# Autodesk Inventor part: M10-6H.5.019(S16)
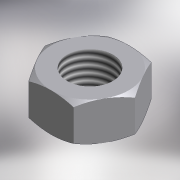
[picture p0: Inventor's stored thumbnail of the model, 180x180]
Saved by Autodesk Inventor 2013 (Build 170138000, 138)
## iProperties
Shininess: 0.0
Length Units: 11269
Angle Units: 11279
Time Units: 11290
Mass Units: 11283
Length Display Precision: 3
Angle Display Precision: 2
Created: 2001-04
Material: Steel, Mild
Description: Гайка М10-6H.5.019 (S16) ГОСТ 5915-70
Document SubType Name: Modeling
Designer: tevgeniy
Mass: 11.2552 g
Surface Area: 10.7859 cm^2
Volume: 1.43196 cm^3
Density: 7.86 g/cm^3
Density: 0.0
Volumn: 0.0
Area: 0.0
PropertySet Name: Model Information
Control State: 0
Master: False
Checked Out: True
Checked Out Date: 2008-10-15
Last Check In Date: 2008-10-15
Author: tevgeniy
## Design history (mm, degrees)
node "ExtrusionBlind1" dims "d6" = 8.4, "d7" = 0
  sketch "Sketch1"
    geometry: L1 (484.39, 469.325)-(474.575, 469.325); L2 (489.297, 460.825)-(484.39, 469.325); L3 (484.39, 452.325)-(489.297, 460.825); L4 (474.575, 452.325)-(484.39, 452.325); L5 (469.667, 460.825)-(474.575, 452.325); L6 (474.575, 469.325)-(469.667, 460.825); C1 r 8.5 at (479.482, 460.825)
    constraints: 12 end point, 6 tangent, 3 parallel, 1 centre point, 1 horizontal, 1 other
    dimensions: "d1" = 120 deg angle of L1 L2; "d3" = 120 deg angle of L5 L6; "d5" = 17 diameter of C1; "d27" = 17 distance between parallel lines of L4 L1 (derived)
node "ExtrusionThru1" dims "d14" = 0.13, "d15" = 0
  sketch "Sketch2"
    geometry: L1 (-472.982, -455.084)-(-472.482, -455.95); L2 (-479.377, -452.325)-(-478.377, -452.325); L3 (-489.203, -460.662)-(-488.703, -459.796); C1 r 5 at (-479.482, -460.825); C2 r 8.5 at (-479.482, -460.825)
    constraints: 6 end point, 3 tangent, 2 centre point, 1 coincident
    dimensions: "d13" = 10 diameter of C1
node "WorkAxis1"
node "WorkPlane1"
node "RevolutionAngle1" dims "d24" = 360 deg
  sketch "Sketch3"
    geometry: L1 (0, 0)-(0, 8.4); L2 (8.5, 0)-(0, 0); L3 (9.815, 0.759)-(8.5, 0); L4 (9.815, 7.641)-(9.815, 0.759); L5 (8.5, 8.4)-(9.815, 7.641); L6 (0, 8.4)-(8.5, 8.4); L7 (0, 8.4)-(-1, 8.4); L8 (-0.105, 0)-(-1.105, 0); L9 (9.815, 8.4)-(9.815, 7.4); L10 (0, 17.846)-(0, -9.446); L11 (0, 17.846)-(0, -9.446)
    constraints: 22 end point, 4 collinear, 2 horizontal, 2 vertical
    dimensions: "d17" = 8.5 distance of L1.end L5.start; "d19" = 30 deg angle of L6 L5; "d21" = 30 deg angle of L3 L2; "d23" = 0 horizontal distance of L5.start L2.start
thread "Thread1" dims "d25" = 10, "d26" = 0
body "Solid1"
other parameters: "d0" = 120 deg (derived), "d2" = 120 deg (derived), "d4" = 17 (derived), "d8" = 0, "d9" = 0, "d10" = 0, "d11" = 0, "d16" = 8.5 (derived), "d18" = 30 deg (derived), "d20" = 30 deg (derived), "d22" = 0 (derived), "d28" = 0
